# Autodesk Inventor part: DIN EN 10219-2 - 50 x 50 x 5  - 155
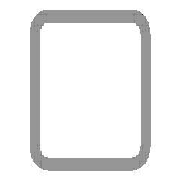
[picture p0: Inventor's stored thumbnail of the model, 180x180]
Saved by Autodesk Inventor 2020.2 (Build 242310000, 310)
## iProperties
Created: 2019-12
Part Number: DIN EN 10219-2 - 50 x 50 x 5  - 155
Material: Generisch
Description: Kaltgeformte, geschweißte Baustahl-Hohlprofile aus unlegiertem Feinkorn-Baustahl
Document SubType Name: Modeling
Standard: DIN
Designer: lutzd
Standard Revision: 2006-07
Standards Organization: DIN
Language: de-DE
Size Designation: 50 x 50 x 5
Categories: <MemberInstance><Categories><Category DisplayName="Profile" InternalName="089c4875-fa83-4c05-b084-43b9cc11f5ed" Mnemonic="GRDR"><CategoryParameter DisplayName="
Stock Number: 50 x 50 x 5
Mass: 129.521 g
Surface Area: 534.796 cm^2
Volume: 129.521 cm^3
Density: 1 g/cm^3
Appearance: Vorgabe
G_L: 155,000 mm
G_W: 50,000 mm
G_H: 50,000 mm
Mass: 0,13 kg
VLT_Material: Generisch
DocNumber: ADSK-014440
Folder: .
_CCFamilyMember: 16
_CCFamilyDisplayName: DIN EN 10219-2 (Quadratisches Hohlprofil - Kaltgeformt) - Kaltgeformte, geschweißte Baustahl-Hohlprofile aus unlegiertem Feinkorn-Baustahl
_FrameMemberDoc: Frame Member File
_Version: 15.0.0
_GetPNFromCC: 1
IsCustomPart: 1
Title: Profil-Bauteil
Author: lutzd
Revision Number: -
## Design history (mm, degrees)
node "Startebene"
node "Endebene"
sketch "Skizze"
  geometry: L1 (-25, -15)-(-25, 15); L2 (-15, 25)-(15, 25); L3 (25, 15)-(25, -15); L4 (15, -25)-(-15, -25); L5 (-15, 20)-(15, 20); L6 (20, 15)-(20, -15); L7 (15, -20)-(-15, -20); L8 (-20, -15)-(-20, 15); L9 (0, 37.899)-(0, -37.899) reference; L10 (-37.899, 0)-(37.899, 0) reference; A1 r 10 centre (-15, -15) between (-25, -15) and (-15, -25); A2 r 10 centre (-15, 15) between (-15, 25) and (-25, 15); A3 r 10 centre (15, 15) between (25, 15) and (15, 25); A4 r 10 centre (15, -15) between (15, -25) and (25, -15); A5 r 5 centre (-15, 15) between (-15, 20) and (-20, 15); A6 r 5 centre (15, 15) between (20, 15) and (15, 20); A7 r 5 centre (15, -15) between (15, -20) and (20, -15); A8 r 5 centre (-15, -15) between (-20, -15) and (-15, -20)
  constraints: 16 end point, 16 point on circle, 8 centre point, 8 tangent, 4 parallel, 3 equal radius, 2 perpendicular, 7 other
  dimensions: "d7" = 10 radius of A1 (= G_IR); "d10" = 50 distance between parallel lines of L2 L4 (= G_H); "d11" = 50 distance between parallel lines of L1 L3 (= G_W); "d12" = 5 distance between parallel lines of L3 L6 (= G_T); "d15" = 25 distance between parallel lines of L2 L10 (= 0.5 x d10); "d16" = 25 distance between parallel lines of L9 L3 (= 0.5 x d11)
extrude "Körper" new body sketch "Skizze" stored distance "d3" = 155 (= G_L); taper "d4" = 0 deg
node "Driven Length"
  sketch "Sketch3"
    geometry: L1 (0, 0)-(10, 0) reference
    constraints: 2 end point, 1 horizontal
  workplane "Work Plane3"
  sketch "Sketch4"
    geometry: L1 (-2, 0)-(12, 0) reference; L2 (-2, 155)-(12, 155) reference
    dimensions: "d18" = 155 distance between parallel lines of L1 L2 (derived)
body "Solid1"
other parameters: "G_W" = 50 [user parameter; used in 1 equation term], "G_H" = 50 [user parameter; used in 1 equation term], "G_T" = 5 [user parameter; used in 1 equation term], "G_IR" = 10 [user parameter; used in 1 equation term], "G_L" = 155 (= d18) [user parameter; used in 1 equation term], "G_OFFSET_START" = 0 [user parameter; used in 1 equation term], "G_OFFSET_END" = 0 [user parameter; used in 1 equation term], "d13" = 0 (computed from G_OFFSET_START), "d14" = 155 (= G_OFFSET_END + B_L), "B_L" = 155 [user parameter; used in 1 equation term], "d17" = 90 deg
